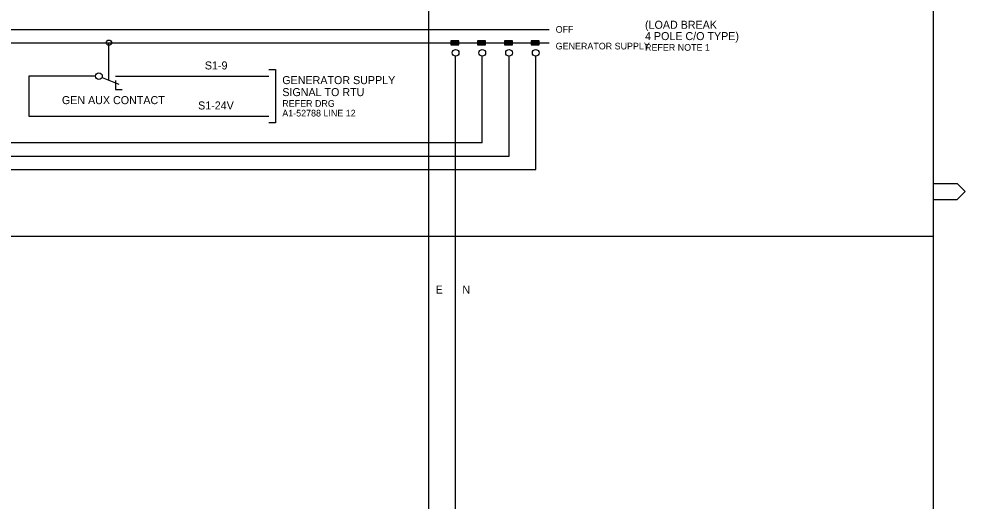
# Model space of a CAD drawing. Extents: x 0 to 841, y 0 to 594.
# Drawn here: x 486.2 to 841, y 180.7 to 361.4 of the extents above; entities that cross this region are included whole.
import ezdxf

# ---------------------------------------------------------------- set-up
doc = ezdxf.new("R2010")
doc.units = 0
for name, color, linetype in [('A1BORDER', 7, 'Continuous'), ('Level 1', 7, 'Continuous'), ('Level 10', 7, 'Continuous')]:
    doc.layers.add(name, color=color, linetype=linetype)

msp = doc.modelspace()

# ---------------------------------------------------------------- linework, layer by layer
at = {"layer": 'A1BORDER'}
for p, q in [((829, 581), (829, 15)), ((829, 299.76), (838, 299.76)), ((838, 299.76), (841, 296.76)), ((838, 293.76), (841, 296.76)), ((829, 293.76), (838, 293.76))]:
    msp.add_line(p, q, dxfattribs=at)
at = {"layer": 'Level 1'}
for p, q in [((640, 110), (640, 545)), ((87.5, 357.5), (685, 357.5)), ((87.5, 352.5), (685, 352.5)), ((520, 338.5), (520, 352.5)), ((648.25, 352.98), (651.25, 352.98)), ((648.25, 352.68), (651.25, 352.68)), ((648.25, 352.38), (651.25, 352.38)), ((648.25, 352.08), (651.25, 352.08)), ((648.25, 351.78), (651.25, 351.78)), ((658.25, 352.98), (661.25, 352.98)), ((658.25, 352.68), (661.25, 352.68)), ((658.25, 352.38), (661.25, 352.38)), ((658.25, 352.08), (661.25, 352.08)), ((658.25, 351.78), (661.25, 351.78)), ((668.25, 352.98), (671.25, 352.98)), ((668.25, 352.68), (671.25, 352.68)), ((668.25, 352.38), (671.25, 352.38)), ((668.25, 352.08), (671.25, 352.08)), ((668.25, 351.78), (671.25, 351.78)), ((678.25, 352.98), (681.25, 352.98)), ((678.25, 352.68), (681.25, 352.68)), ((678.25, 352.38), (681.25, 352.38)), ((678.25, 352.08), (681.25, 352.08)), ((678.25, 351.78), (681.25, 351.78)), ((650, 110), (650, 347.5)), ((660, 315), (660, 347.5)), ((670, 310), (670, 347.5)), ((680, 305), (680, 347.5)), ((515, 340), (490, 340)), ((490, 340), (490, 325)), ((525, 340), (580, 340)), ((490, 325), (580, 325)), ((660, 315), (110, 315)), ((120, 310), (670, 310)), ((130, 305), (680, 305)), ((28, 280), (829, 280))]:
    msp.add_line(p, q, dxfattribs=at)
for points in [[(648.25, 351.75), (651.25, 351.75), (651.25, 353.25), (648.25, 353.25)], [(658.25, 351.75), (661.25, 351.75), (661.25, 353.25), (658.25, 353.25)], [(668.25, 351.75), (671.25, 351.75), (671.25, 353.25), (668.25, 353.25)], [(678.25, 351.75), (681.25, 351.75), (681.25, 353.25), (678.25, 353.25)]]:
    msp.add_lwpolyline(points, close=True, dxfattribs=at)
msp.add_lwpolyline([(580, 342.5), (582.5, 342.5), (582.5, 322.5), (580, 322.5)], dxfattribs=at)
for centre, radius in [((520, 352.5), 1), ((650, 348.75), 1.25), ((660, 348.75), 1.25), ((670, 348.75), 1.25), ((680, 348.75), 1.25)]:
    msp.add_circle(centre, radius, dxfattribs=at)
at = {"layer": 'Level 10'}
for p, q in [((517.41, 339.54), (523.75, 337)), ((522.5, 340), (525, 340)), ((522.5, 338.37), (522.5, 335)), ((522.5, 335), (525, 335))]:
    msp.add_line(p, q, dxfattribs=at)
msp.add_circle((516.25, 340), 1.25, dxfattribs=at)

# ---------------------------------------------------------------- texts
at = {"layer": 'Level 1'}
for s, height, p in [('OFF', 2.5, (687.5, 356.25)), ('(LOAD BREAK', 3, (721, 357.75)), ('4 POLE C/O TYPE)', 3, (721, 353.5)), ('GENERATOR SUPPLY', 2.5, (687.5, 350)), ('REFER NOTE 1', 2.5, (721, 349.5)), ('S1-9', 3, (555.97, 342.5)), ('GENERATOR SUPPLY', 3, (585, 337)), ('SIGNAL TO RTU', 3, (585, 332.5)), ('GEN AUX CONTACT', 3, (502.37, 329.5)), ('S1-24V', 3, (553.43, 327.5)), ('REFER DRG', 2.5, (585, 328.49)), ('A1-52788 LINE 12', 2.5, (585, 324.87)), ('E', 3, (642.5, 258.5)), ('N', 3, (652.5, 258.5))]:
    msp.add_text(s, height=height, dxfattribs=at).set_placement(p)

doc.saveas('drawing.dxf')
